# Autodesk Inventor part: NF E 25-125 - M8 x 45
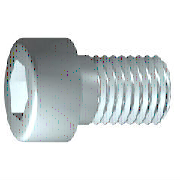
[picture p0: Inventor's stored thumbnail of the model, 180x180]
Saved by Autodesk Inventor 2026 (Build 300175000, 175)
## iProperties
Created: 2025-01
Part Number: NF E 25-125 - M8 x 45
Material: Acier, doux
Description: Tête cylindrique fendue - Produit de classe A - Symbole C S
Document SubType Name: Modeling
Standard: NF E 25-125
Designer: thierry.jost
Standards Organization: AFNOR
Language: fr-FR
Size Designation: M8 x 45
Categories: <MemberInstance><Categories><Category DisplayName="Visserie" InternalName="e4da775c-781d-43d5-af7c-5136215cf5a6" Mnemonic="FSTN"><Category DisplayName="Vis" Int
Density: 7.85 g/cm^3
Appearance: Semi-poli
IsCustomPart: 0
Author: thierry.jost
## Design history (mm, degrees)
body "Solid1"
workplane "Work Plane1"
fillet "Fillet2" dims "d30" = 0.1 (= R)
revolve "Corps" stored, may be unused: angle "d10" = 90 deg
sketch "Esquisse2"
  geometry: L1 (0, -9.1)-(0, 9.1) reference; L2 (-9.1, 0)-(9.1, 0) reference; L3 (3.464, 0)-(1.732, -3); L4 (1.732, -3)-(-1.732, -3); L5 (-1.732, -3)-(-3.464, 0); L6 (-3.464, 0)-(-1.732, 3); L7 (-1.732, 3)-(1.732, 3); L8 (1.732, 3)-(3.464, 0); 2 further points
  constraints: 12 end point, 1 coincident, 1 horizontal alignment, 1 point on line, 12 other
extrude "Rainure" join sketch "Esquisse2" stored distance "d11" = 10; taper "d12" = 0 deg
fillet "Congé1" dims "d17" = 0.8 (= RR)
feature "Filetage" dims "d13" = 28 (= GEL), "d14" = 0
chamfer "Chanfrein1" distance "d15" = 0.76681 (= -0.5 x SPD + 0.5 x GD); stored, may be unused: second distance "d16" = 0.76681 (= GUL), angle "d27" = 45 deg
sketch "Esquisse1"
  geometry: L1 (-2, 0)-(45, 0); L2 (45, 0)-(45, 4); L3 (45, 4)-(17, 4); L4 (17, 4)-(16.233, 4); L5 (16.233, 4)-(0, 4); L6 (0, 4)-(0, 6.5); L7 (0, 6.5)-(-8, 6.5); L8 (-8, 6.5)-(-8, 3.464); L9 (-8, 3.464)-(-4, 3.464); L10 (-4, 3.464)-(-2, 0); L11 (-18.6, 0)-(55.6, 0) reference; L12 (0, -1.3)-(0, 7.8) reference; L13 (17, 4)-(0, 4)
  constraints: 22 end point, 6 parallel, 2 collinear, 2 perpendicular, 1 horizontal, 1 point on line
  dimensions: "d1" = 28 distance from line of L3.end L2 (= GEL); "d2" = 0.76691 distance of L4.end L3.end (computed from GAL); "d3" = 8 distance between parallel lines of L8 L6 (= KOH); "d4" = 4 distance of L8.end L9.end (= INTI); "d5" = 60 deg angle of L10 L1; "d6" = 8 diameter of L3 L1 (= GD); "d7" = 8 diameter of L5 L1 (= BDM); "d8" = 6.9282 diameter of L9 L1 (= 1.1547 x SW); "d9" = 13 diameter of L7 L1 (= KOD); "d26" = 45 distance between parallel lines of L12 L2 (= NLG)
other parameters: "GD" = 8 (= NND) [user parameter; used in 2 equation terms], "NLG" = 45 [user parameter; used in 1 equation term], "GEL" = 28 [user parameter; used in 2 equation terms], "KOD" = 13 [user parameter; used in 1 equation term], "KOH" = 8 (= NND) [user parameter; used in 1 equation term], "INTI" = 4 [user parameter; used in 1 equation term], "GAL" = 0.76681 (= 0.61345 x PTC) [user parameter; used in 1 equation term], "GUL" = 0.76681 (= 0.61345 x PTC) [user parameter; used in 1 equation term], "BDM" = 8 (= NND) [user parameter; used in 1 equation term], "SW" = 6 [user parameter; used in 2 equation terms], "RR" = 0.8 [user parameter; used in 1 equation term], "SPD" = 6.46637 (= NND - 1.2269 x PTC) [user parameter; used in 1 equation term], "d19" = 0, "d28" = 0, "d29" = 0, "R" = 0.1 [user parameter; used in 1 equation term], "TOA" = 30 deg [user parameter], "GD1" = 6.46637 (= THREADDIA - 1.2269 x PTC) [user parameter], "THREADDIA" = 8 [user parameter; used in 1 equation term], "FAWI" = 45 deg [user parameter], "TPU" = 8 (computed from PTC) [user parameter], "PTC" = 1.25 [user parameter; used in 5 equation terms], "NND" = 8 [user parameter; used in 4 equation terms], "E0" = 6.93 (= 1.155 x SW) [user parameter]
